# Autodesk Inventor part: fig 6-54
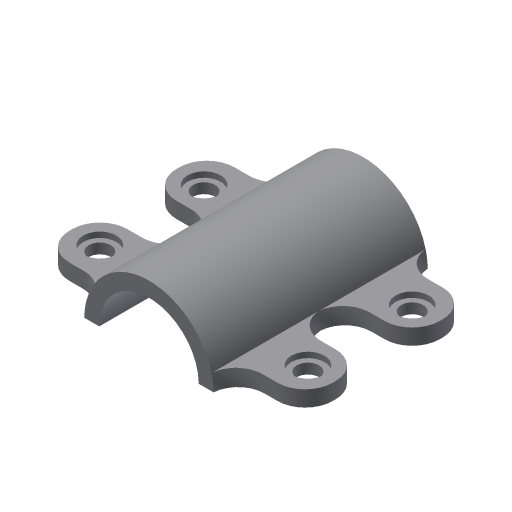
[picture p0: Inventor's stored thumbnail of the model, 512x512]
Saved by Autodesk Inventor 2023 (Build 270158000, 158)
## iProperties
Created: 2004-05
Part Number: fig 6-54
Document SubType Name: Modeling
Designer: CADCIM Technologies
Manufacturer: Standard
Standards Organization: Custom
Density: 1 g/cm^3
Material: Generic
Appearance: Default
Author: CADCIM Technologies
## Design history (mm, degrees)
node "Sketch1"
sketch "Sketch2"
  geometry: L1 (23.378, 0)-(17.996, 0); L2 (-17.996, 0)-(-23.378, 0); A1 r 23.378 centre (0, 0) between (23.378, 0) and (-23.378, 0); A2 r 17.996 centre (0, 0) between (17.996, 0) and (-17.996, 0)
  constraints: 4 end point, 4 point on circle, 2 centre point, 1 collinear, 1 horizontal
extrude "Extrusion1" new body sketch "Sketch2" stored distance "d0" = 38.75; taper "d1" = 0 deg
sketch "Sketch3"
  geometry: L1 (23.378, 0)-(17.996, 0); L2 (-17.996, 0)-(-23.378, 0) reference; L3 (-23.378, 0)-(-47.662, 0); L4 (-47.662, 0)-(-47.662, 5.722); L5 (-47.662, 5.722)-(-22.667, 5.722); A1 r 17.996 centre (0, 0) between (17.996, 0) and (-17.996, 0) reference; A2 r 23.378 centre (0, 0) between (23.378, 0) and (-23.378, 0) reference; 1 further point
  constraints: 10 end point, 5 point on circle, 2 centre point, 1 collinear, 1 horizontal, 1 midpoint, 1 parallel, 1 perpendicular, 3 other
extrude "Extrusion2" join sketch "Sketch3" stored distance "d2" = 21; taper "d3" = 0 deg
fillet "Fillet1" dims "d4" = 10
hole "Hole1" diameter "d7" = 8; stored, may be unused: countersink angle "d11" = 90 deg, drill point angle "d13" = 118 deg; dims "d5" = 10, "d6" = 10, "d8" = 6, "d9" = 12, "d10" = 2, "d12" = 12
fillet "Fillet2" dims "d14" = 9.5
mirror "Mirror1"
mirror "Mirror2"
body "Solid1"
